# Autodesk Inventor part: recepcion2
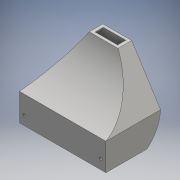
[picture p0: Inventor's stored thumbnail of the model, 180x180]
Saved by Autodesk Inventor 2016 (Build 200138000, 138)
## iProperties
Created: 2016-06
Part Number: recepcion2
Material: Generic
Document SubType Name: Modeling
Designer: yesi alvarez
Mass: 59.0376 g
Surface Area: 406.626 cm^2
Volume: 59.0376 cm^3
Density: 1 g/cm^3
Appearance: Default
Author: yesi alvarez
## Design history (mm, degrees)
sketch "Sketch2"
  geometry: L1 (0, 0)-(95, 0); L2 (95, 0)-(95, 60); L3 (95, 60)-(0, 60); L4 (0, 60)-(0, 0)
  constraints: 8 end point, 2 parallel, 1 horizontal, 1 perpendicular
  dimensions: "d11" = 95 distance of L3.end L2.end; "d12" = 60 distance of L2.end L1.end
workplane "Work Plane1"
sketch "Sketch3"
  geometry: L1 (31.667, 60)-(63.333, 60); L2 (63.333, 60)-(63.333, 45); L3 (63.333, 45)-(31.667, 45); L4 (31.667, 45)-(31.667, 60); 1 further point
  constraints: 8 end point, 2 parallel, 1 horizontal, 1 perpendicular
  dimensions: "d14" = 60 vertical distance of point (0, 0) L1.start; "d15" = 31.66667 horizontal distance of L1.start point (0, 0); "d16" = 31.66667 distance of L2.end L3.end; "d17" = 15 distance of L1.end L2.end
workplane "Work Plane2"
sketch "Sketch4"
  geometry: L1 (0, 0)-(95, 0); L2 (95, 0)-(95, 60); L3 (95, 60)-(0, 60); L4 (0, 60)-(0, 0)
  constraints: 8 end point, 2 parallel, 1 horizontal, 1 perpendicular
  dimensions: "d19" = 95 distance of L3.end L2.end; "d20" = 60 distance of L2.end L1.end
loft "Loft1" sketch "Sketch4" dims "d21" = 0, "d22" = 90 deg, "d23" = 0, "d24" = 90 deg
sketch "Sketch5"
  geometry: L1 (95, 0)-(95, 60) reference; L2 (0, 0)-(95, 0); L3 (95, 0)-(95, 60); L4 (95, 60)-(0, 60); L5 (0, 60)-(0, 0)
  constraints: 8 end point, 2 parallel, 1 horizontal, 1 perpendicular
  dimensions: "d25" = 95 distance of L4.end L1.end (derived); "d26" = 60 distance of L1.end L2.end (derived)
loft "Loft2" dims "d27" = 0, "d28" = 90 deg, "d29" = 0, "d30" = 90 deg
  node "Edges1"
workplane "Work Plane3"
sketch "Sketch6"
  geometry: L1 (67.082, 0)-(53.666, -26.833) reference; L2 (-22.361, -44.721)-(-8.944, -51.43) reference; L3 (53.666, -26.833)-(0, 0) reference; L4 (53.666, -26.833)-(-8.944, -51.43); A1 r 63.248 centre (41.946, -88.985) between (53.666, -26.833) and (-8.944, -51.43)
  constraints: 2 end point, 2 point on circle, 1 centre point
extrude "Extrusion2" cut sketch "Sketch6" distance "d31" = 100; taper "d32" = 0 deg
sketch "Sketch7"
  geometry: L1 (0, 60)-(0, 0) reference; L2 (30, 60)-(80, 60) reference; L3 (0, 45)-(0, 60); L4 (30, 60)-(30, 0) reference; L5 (30, 60)-(0, 60); A1 r 41.029 centre (31.746, 19.008) between (30, 60) and (0, 45)
  constraints: 4 end point, 2 point on circle, 1 centre point, 1 perpendicular, 1 point on line, 1 vertical
  dimensions: "d33" = 45 distance of L3.start L1.end
extrude "Extrusion3" cut sketch "Sketch7" distance "d34" = 100; taper "d35" = 0 deg
shell "Shell2" dims "d36" = 3
sketch "Sketch8"
  geometry: L1 (92, 0)-(92, 27.775) reference; L2 (3, 0)-(3, 27.775) reference; L3 (0, 0)-(95, 0) reference; L4 (95, 0)-(95, 30) reference; C1 r 1.5 at (89.5, 10.53); C2 r 1.5 at (5.5, 10); 2 further points
  constraints: 2 centre point, 2 coincident
  dimensions: "d39" = 10 distance from line of point (5.5, 10) L3; "d40" = 3 diameter of C1; "d41" = 3 diameter of C2; "d48" = 5.5 distance from line of C1.centre L4
extrude "Extrusion4" cut sketch "Sketch8" distance "d42" = 10; taper "d43" = 0 deg
thread "Thread1" dims "d44" = 10, "d45" = 0
thread "Thread2" dims "d46" = 10, "d47" = 0
body "Solid2"
